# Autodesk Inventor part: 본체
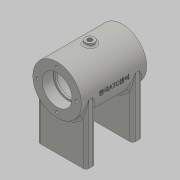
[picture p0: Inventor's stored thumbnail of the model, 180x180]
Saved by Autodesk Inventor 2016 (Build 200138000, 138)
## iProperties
Created: 2020-07
Part Number: 본체
Material: Generic
Document SubType Name: Modeling
Designer: user
Density: 1 g/cm^3
Appearance: Default
Author: user
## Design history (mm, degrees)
sketch "스케치1"
  geometry: C1 r 26 at (0, 0); 1 further point
  constraints: 1 centre point, 1 coincident
  dimensions: "d0" = 52 diameter of C1
extrude "돌출1" new body sketch "스케치1" stored distance "d1" = 70; taper "d2" = 0 deg
hole "구멍1" diameter "d5" = 28; stored, may be unused: countersink angle "d9" = 90 deg, drill point angle "d11" = 0 deg; dims "d6" = 6.35, "d7" = 32, "d8" = 12, "d10" = 14, "d12" = 10, "d13" = 10
hole "구멍2" diameter "d16" = 42; stored, may be unused: countersink angle "d20" = 90 deg, drill point angle "d22" = 0 deg; dims "d14" = 10, "d15" = 10, "d17" = 6.35, "d18" = 32, "d19" = 12, "d21" = 42
fillet "모깎기1" dims "d23" = 3
fillet "모깎기2" dims "d24" = 0.3
node "작업 평면1"
sketch "스케치2"
  geometry: L1 (-26, 0)-(-26, -64); L2 (-26, -64)-(26, -64); L3 (26, -64)-(26, 0); C1 r 20.236 at (0, 0) reference; A1 r 26 centre (0, 0) between (-26, 0) and (26, 0) reference; 1 further point
  constraints: 6 end point, 2 perpendicular, 2 point on circle, 2 tangent, 1 vertical
  dimensions: "d26" = 64 distance from line of point (0, 0) L2; "d27" = 52 distance of L1.end L2.end (derived)
extrude "돌출2" join sketch "스케치2" distance "d28" = 10; taper "d29" = 0 deg
fillet "모깎기3" dims "d30" = 3
fillet "모깎기4" dims "d31" = 3
sketch "스케치3" dims "d32" = 42
  geometry: L1 (0, 0)-(0, 21); C1 r 26 at (0, 0) reference; 1 further point
  constraints: 2 end point, 1 coincident, 1 vertical, 1 vertical alignment, 2 other
hole "구멍3" sketch "스케치3" at (0, 21) diameter "d33" = 3.242; stored, may be unused: countersink angle "d37" = 90 deg, drill point angle "d39" = 118 deg; dims "d34" = 8, "d35" = 32, "d36" = 12, "d38" = 10
node "작업 평면2"
sketch "스케치4"
  geometry: L1 (-26, -35)-(26, -35) reference; L2 (-26, -35)-(-26, 35) reference; 2 further points
  constraints: 1 coincident, 1 other
feature "엠보싱1" sketch "스케치4" dims "d46" = 0.5, "d47" = 0
sketch "스케치5"
  geometry: L1 (-26.429, 1.943)-(-25.93, 1.906) reference; L2 (-25.952, 1.576)-(-26.451, 1.606) reference; L3 (0, 0)-(0, -26); L4 (0, 0)-(9.919, -27.251); C1 r 21 at (0, 0) reference; A1 r 26.5 centre (0, 0) between (-26.429, 1.943) and (-26.451, 1.606) reference; A2 r 26 centre (0, 0) between (-25.952, 1.576) and (-25.93, 1.906) reference; 1 further point
  constraints: 4 end point, 1 point on circle, 1 vertical
  dimensions: "d48" = 29 distance of L3.start L4.end; "d49" = 20 deg angle of L4 L3
  node "절단 모서리 투영2"
node "작업 평면3"
sketch "스케치6"
  geometry: C1 r 6 at (0, 0); 1 further point
  constraints: 1 centre point, 1 coincident
  dimensions: "d50" = 12 diameter of C1
extrude "돌출3" join sketch "스케치6" stored distance "d51" = 10; taper "d52" = 0 deg
hole "구멍4" diameter "d55" = 5.188; stored, may be unused: countersink angle "d59" = 90 deg, drill point angle "d61" = 0 deg; dims "d53" = 10, "d54" = 10, "d56" = 12, "d57" = 32, "d58" = 12, "d60" = 16
fillet "모깎기5" dims "d62" = 2
node "작업 평면4"
sketch "스케치7"
  geometry: C1 r 5 at (0, 0); 1 further point
  constraints: 1 centre point, 1 coincident
  dimensions: "d64" = 10 diameter of C1
extrude "돌출4" join sketch "스케치7" stored distance "d65" = 10; taper "d66" = 0 deg
hole "구멍5" diameter "d69" = 5.188; stored, may be unused: countersink angle "d73" = 90 deg, drill point angle "d75" = 0 deg; dims "d67" = 10, "d68" = 10, "d70" = 12, "d71" = 32, "d72" = 12, "d74" = 16
fillet "모깎기6" dims "d76" = 2
sketch "스케치8"
  geometry: L1 (0, -10)-(46, -10) reference; L2 (49, -3)-(49, -7) reference; L3 (0, 0)-(46, 0) reference; L4 (-3, -3)-(-3, -7) reference; L5 (-3, -5)-(49, -5); A1 r 3 centre (0, -7) between (-3, -7) and (0, -10) reference; A2 r 3 centre (46, -7) between (46, -10) and (49, -7) reference; A3 r 3 centre (46, -3) between (49, -3) and (46, 0) reference; A4 r 3 centre (0, -3) between (0, 0) and (-3, -3) reference; 3 further points
  constraints: 2 end point, 2 midpoint, 2 point on line
  dimensions: "d77" = 5 distance between parallel lines of L5 L3 (derived); "d78" = 20 horizontal distance of point (3, -5) point (23, 20); "d79" = 40 distance of point (43, -5) point (3, -5)
hole "구멍6" sketch "스케치8" at (3, -5), (43, -5) diameter "d80" = 4.134; stored, may be unused: countersink angle "d84" = 90 deg, drill point angle "d86" = 118 deg; dims "d81" = 8, "d82" = 32, "d83" = 12, "d85" = 10
node "솔리드1"
mirror "대칭1"
mirror "대칭2"
pattern_circular "원형 패턴1" dims angle "d41" = 360 deg
mirror "대칭3"
mirror "대칭4"
node "투영된 루프1"
node "절단 모서리 투영1"
other parameters: "d43" = -35.5, "d63" = 29
